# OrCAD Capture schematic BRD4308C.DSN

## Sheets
1 02: Module Pin Assignments: size A3; title: xGM210PB32 Wireless Gecko Module Radio Board; rev: A01; company: Silicon Labs; note: BRD4308C; note: TAB; note: JSH
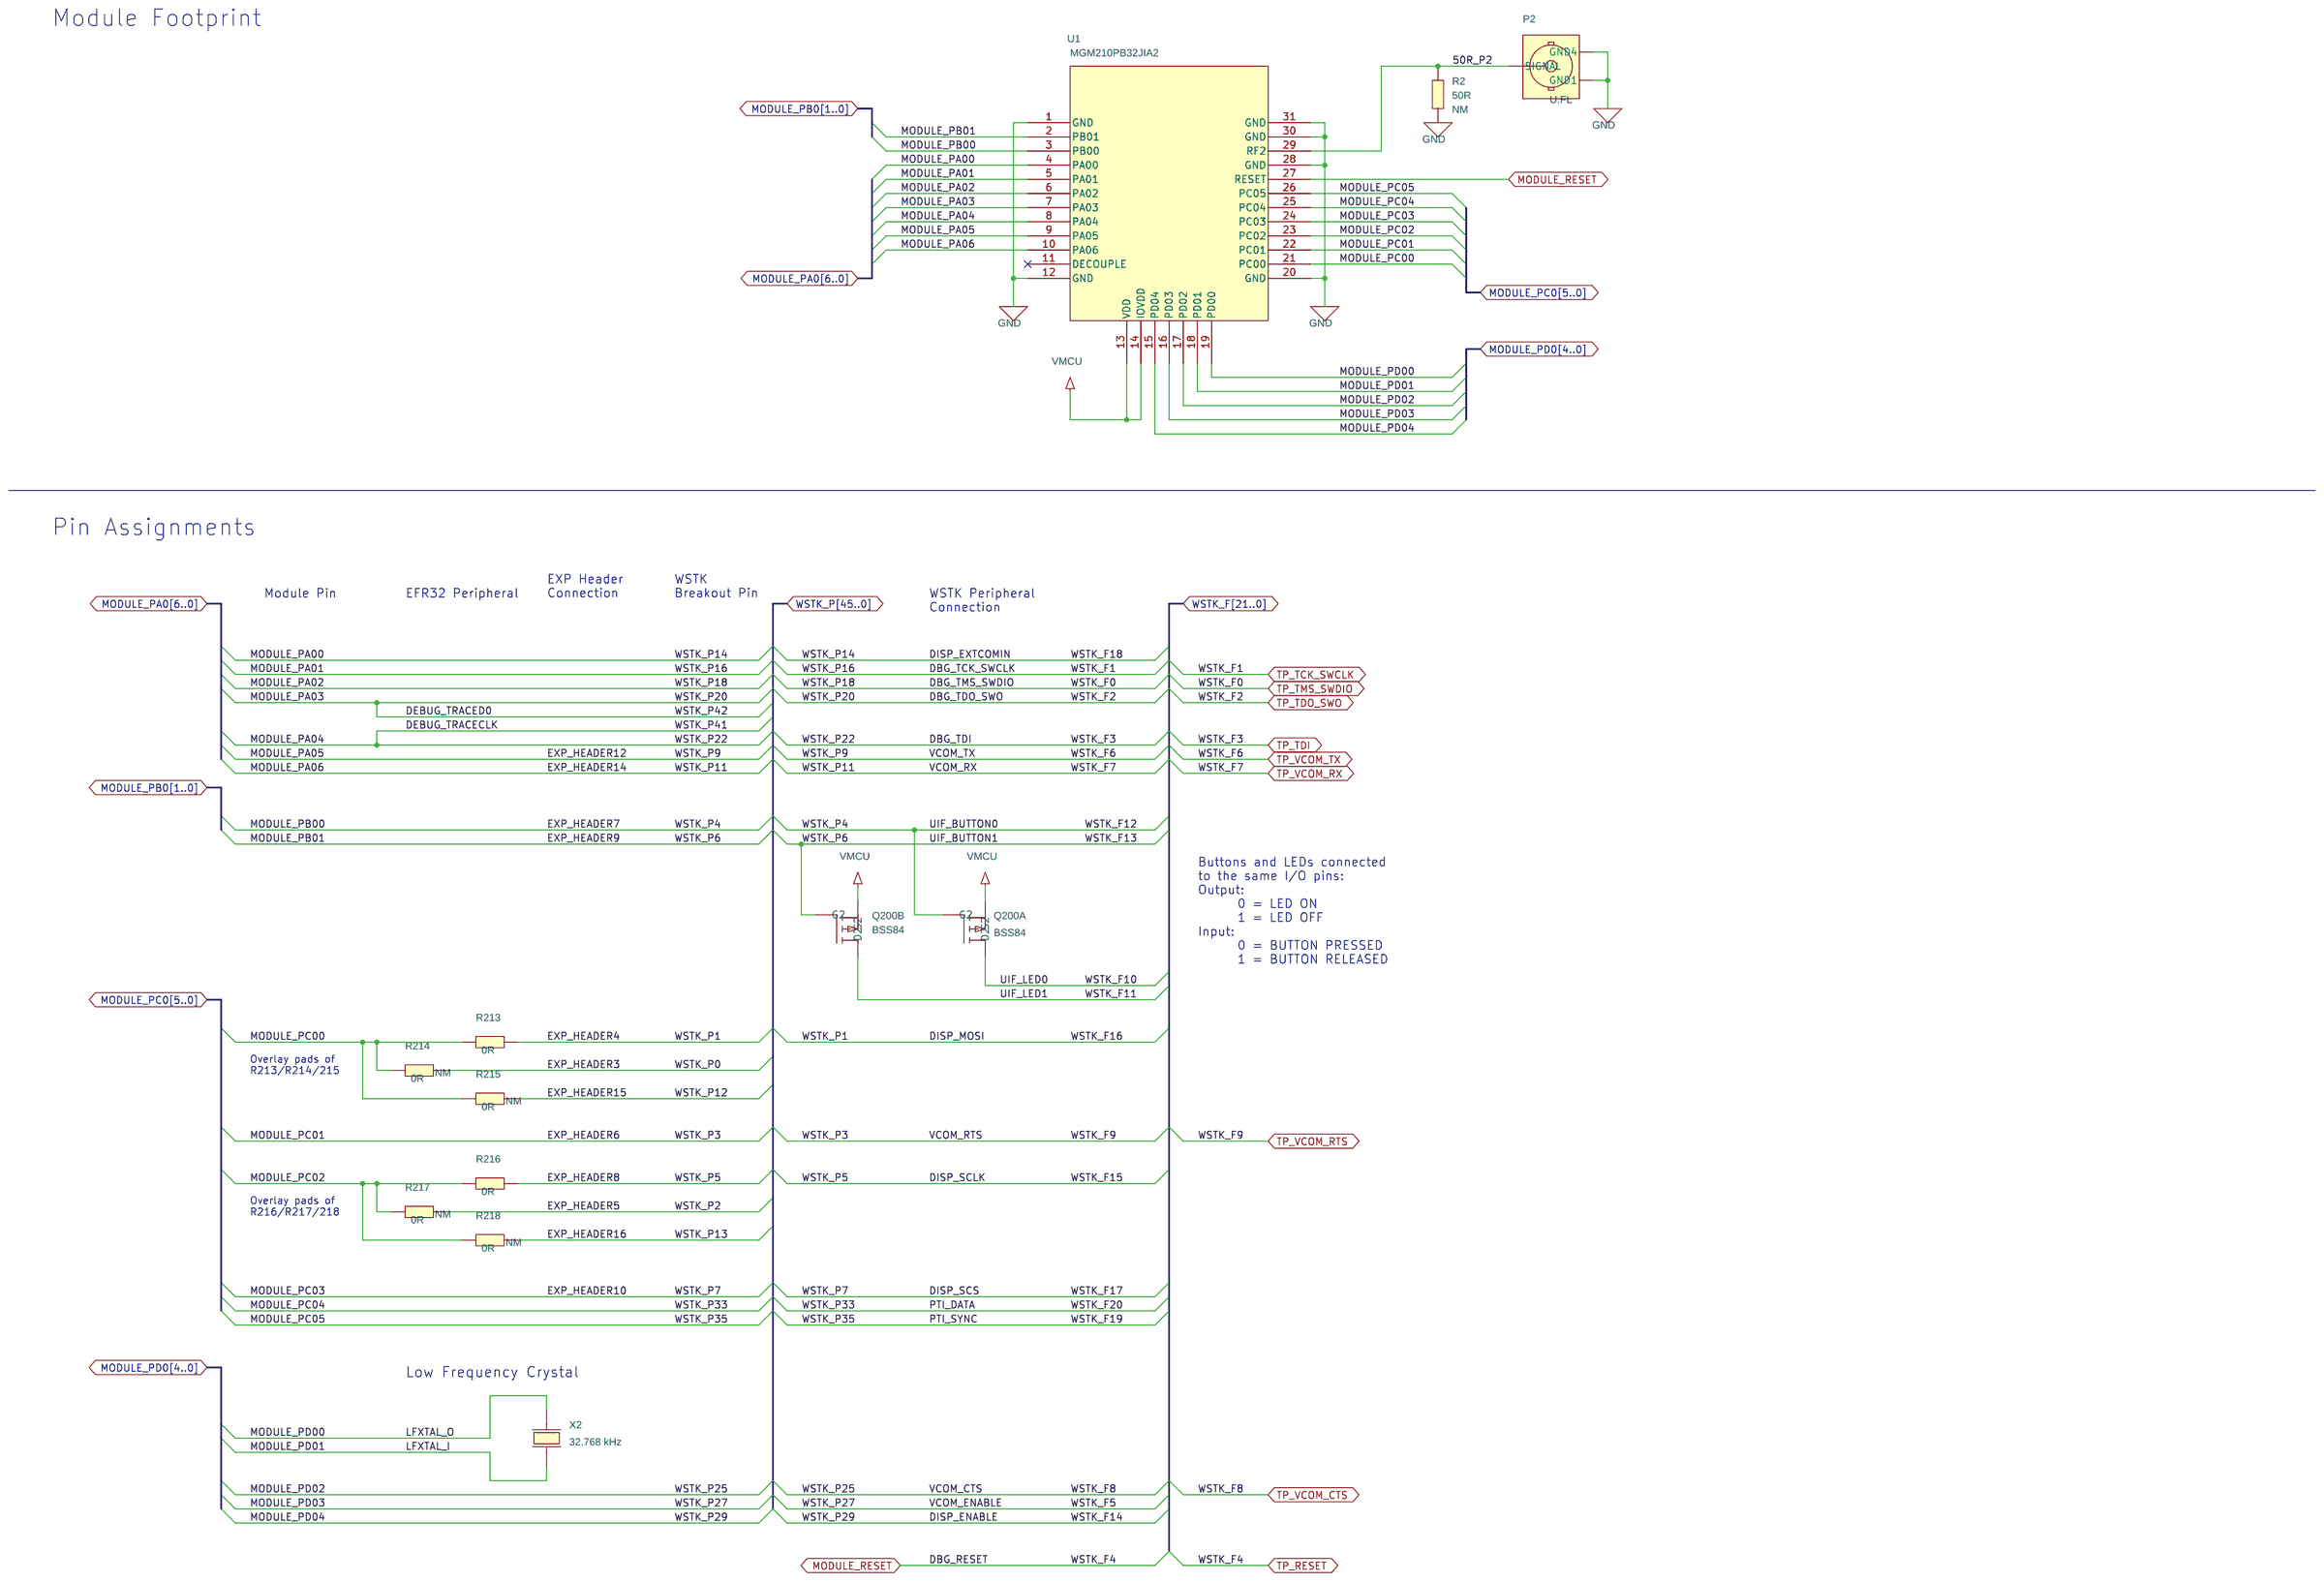
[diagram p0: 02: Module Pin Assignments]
2 01: Title Page
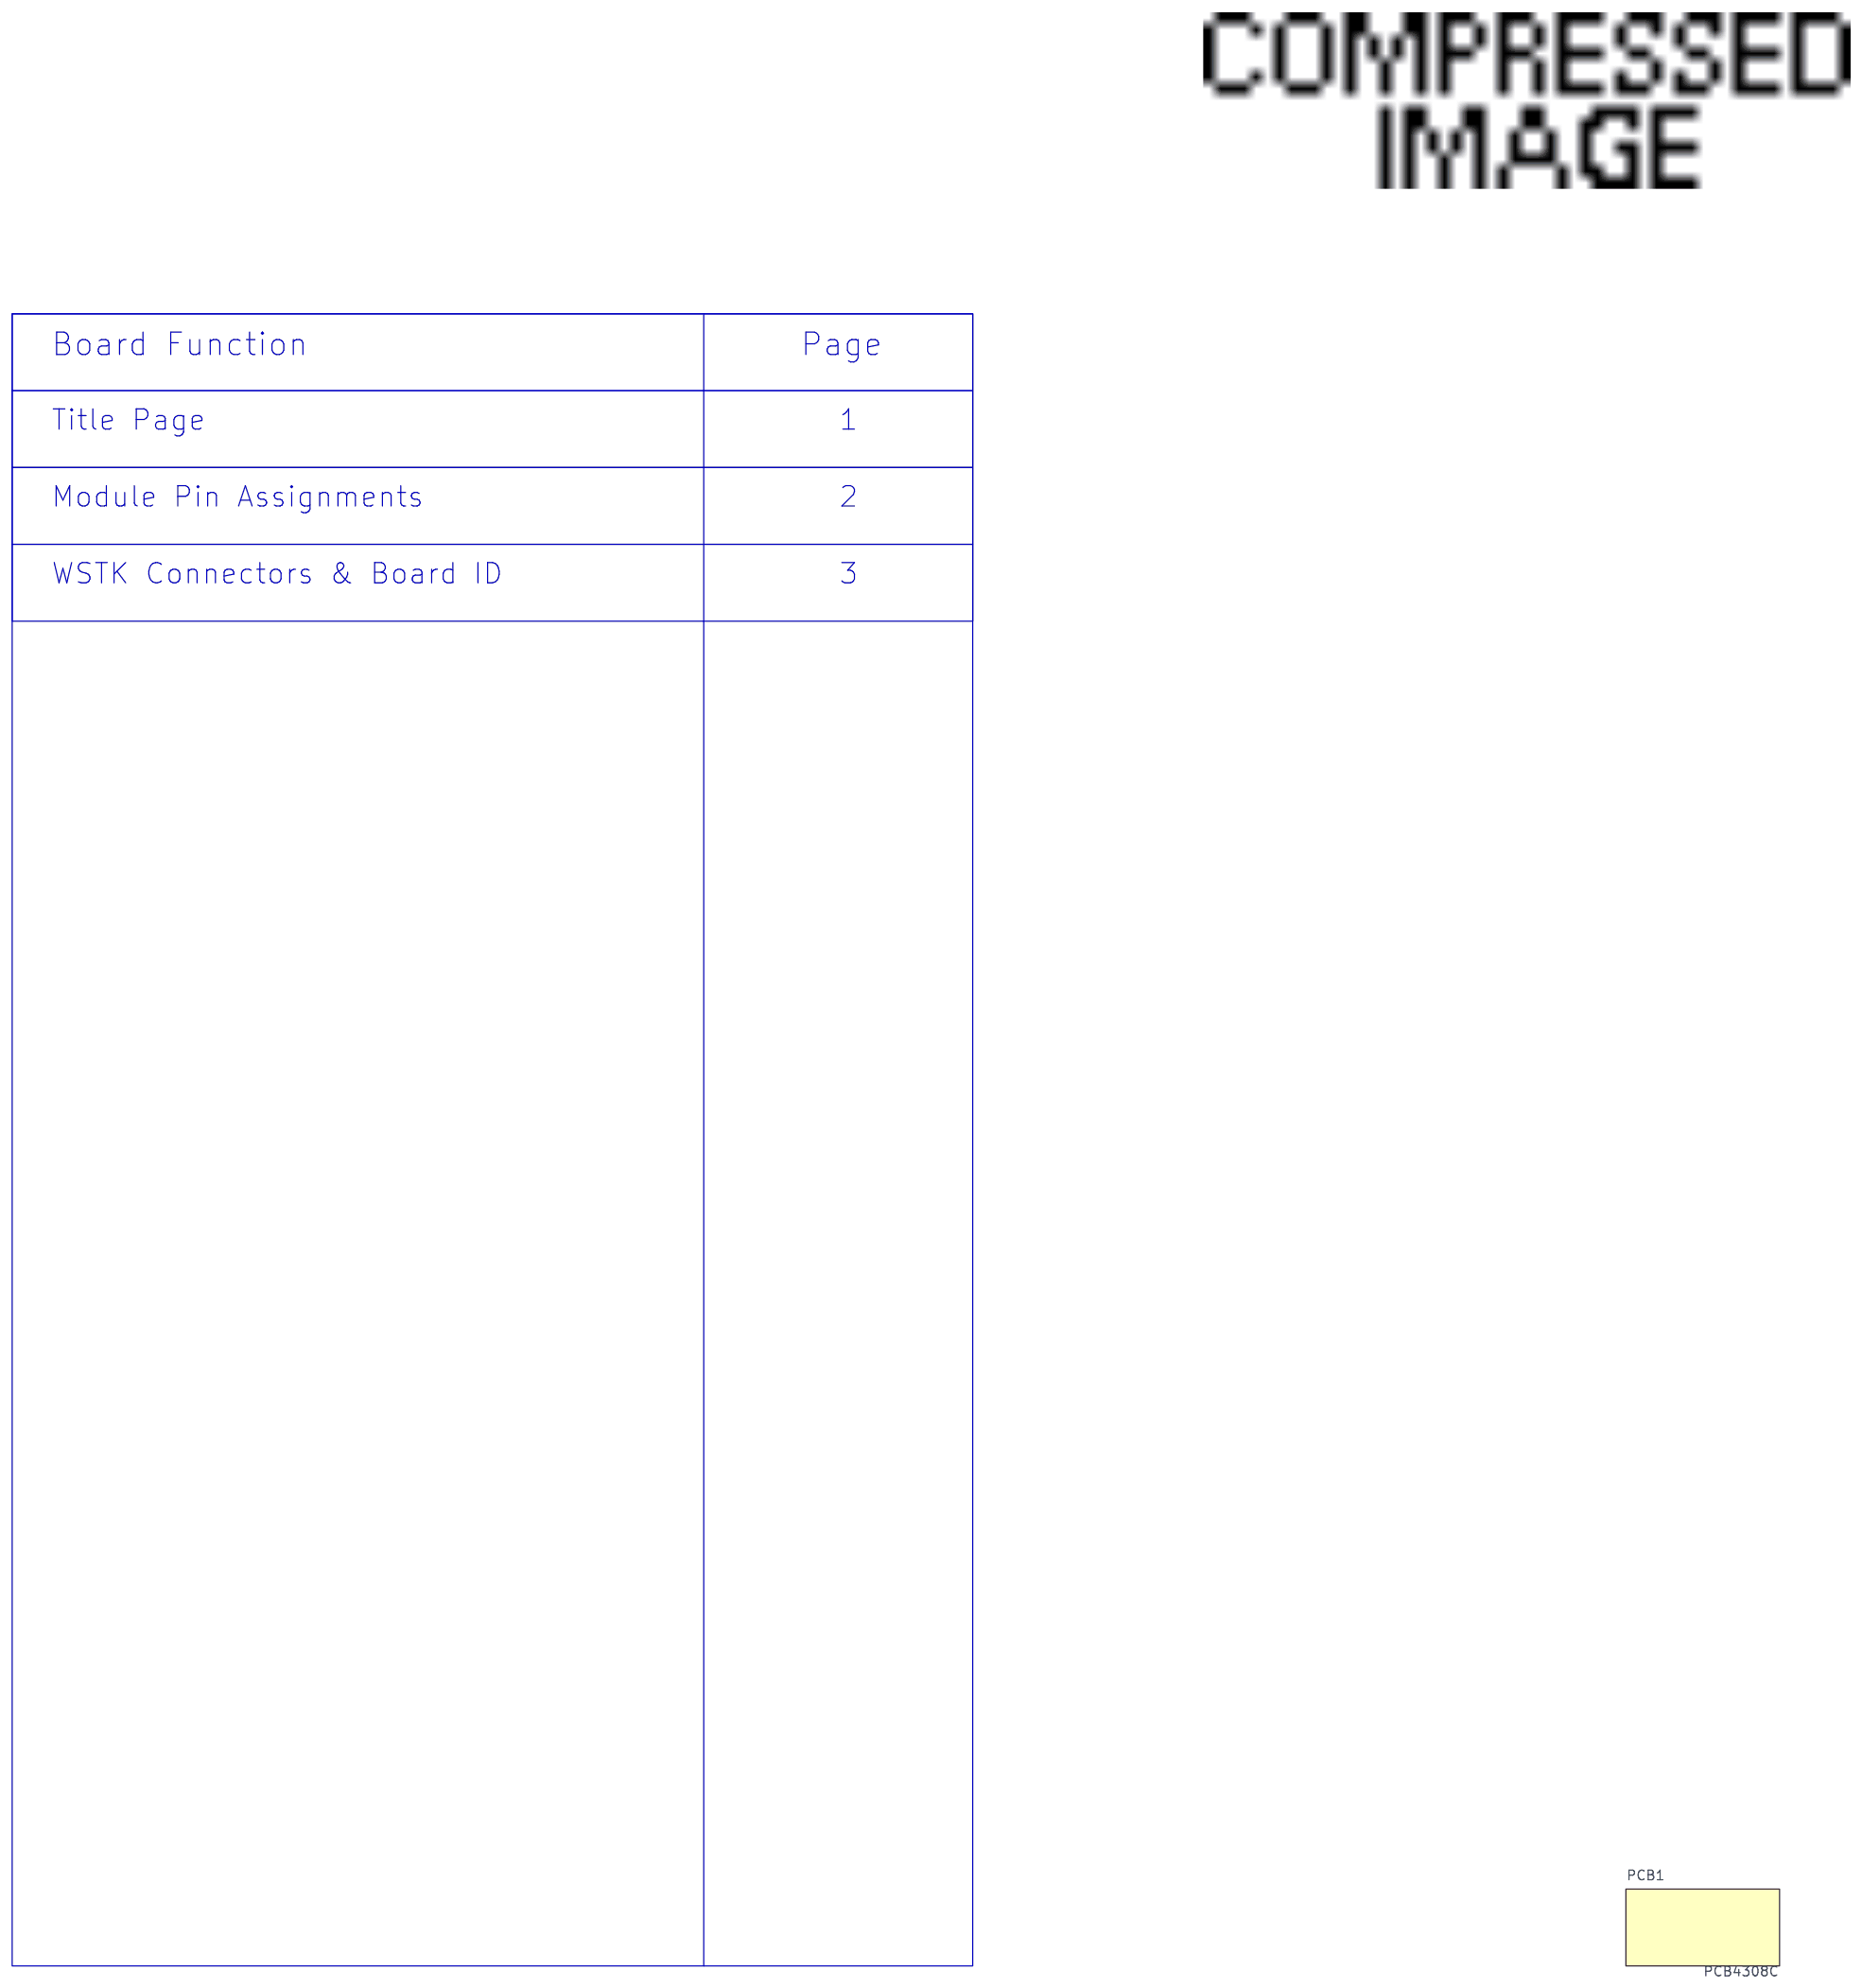
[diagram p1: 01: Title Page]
3 03: WSTK Connectors & Board ID: size A3
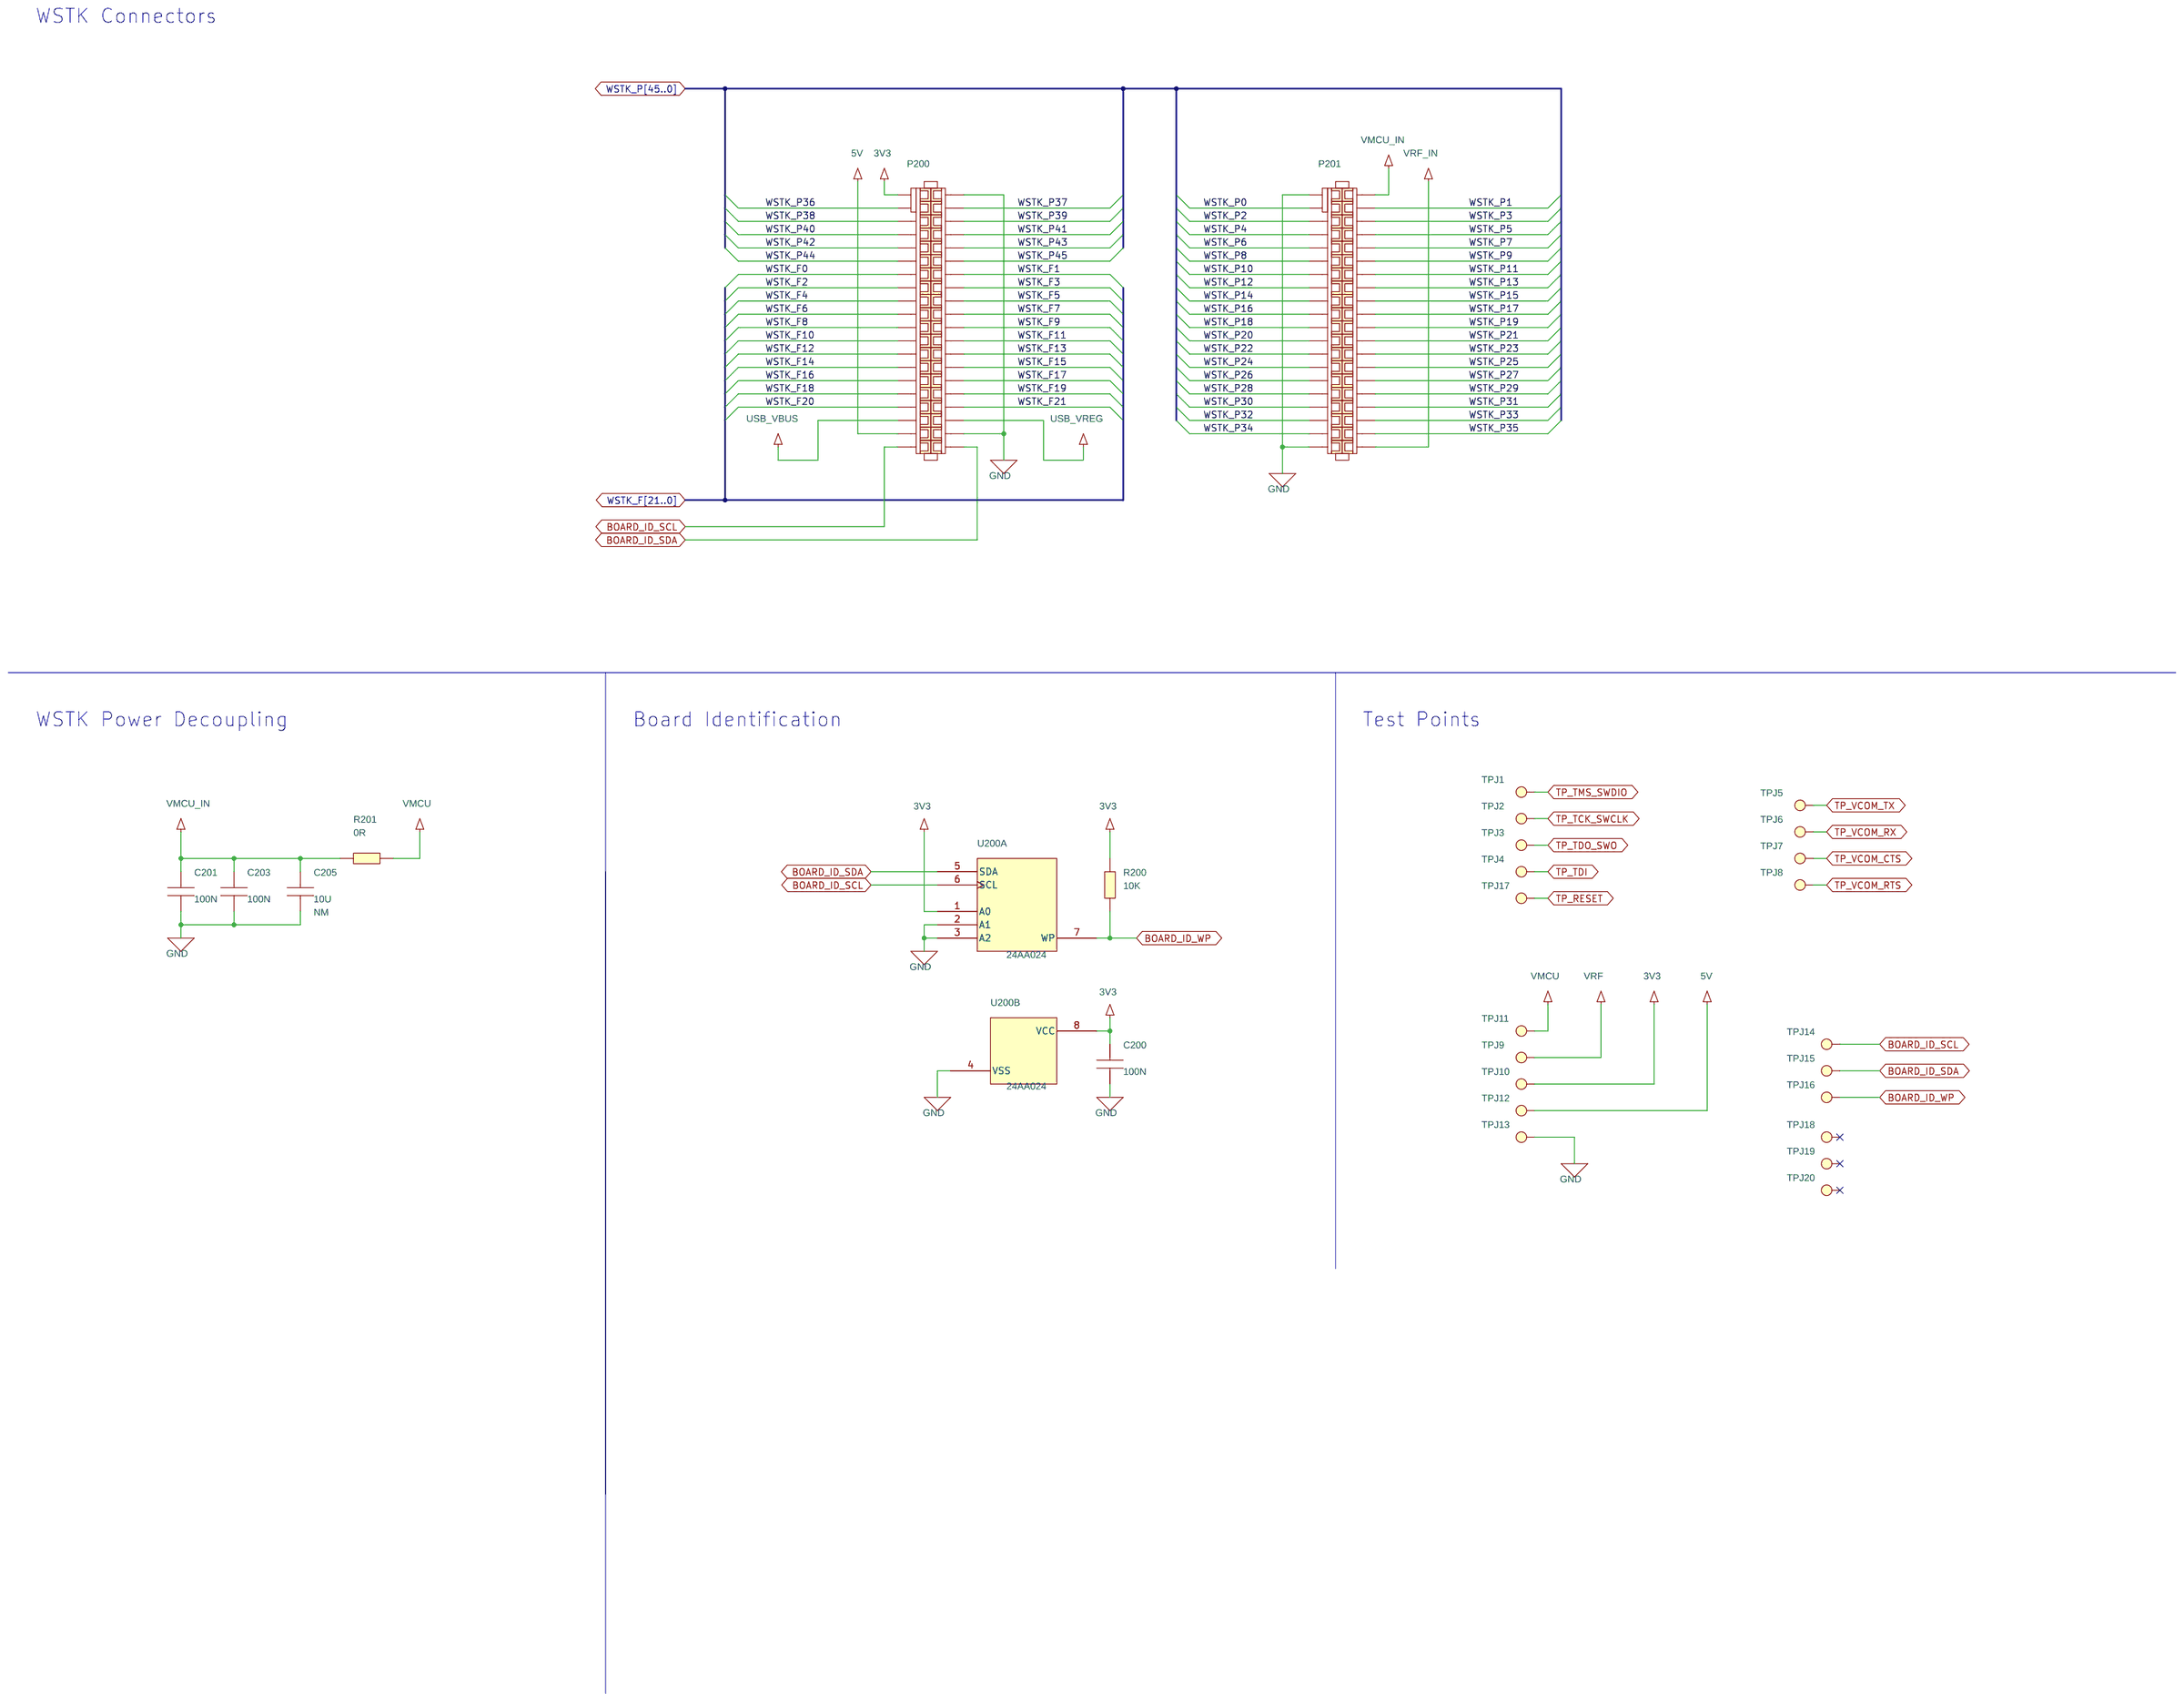
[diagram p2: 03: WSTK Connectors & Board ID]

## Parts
sheet 01: Title Page
PCB1  PCB4308C  [N/A]
sheet 02: Module Pin Assignments
P2  U.FL  [COAX_HIROSE_U.FL_CL331-0471]
Q200  BSS84  [SOT-363]  (sections A,B)
R2  50R  [R0402_L]
R213  0R  [R0402_L]
R214  0R  [R0402_L]
R215  0R  [R0402_L]
R216  0R  [R0402_L]
R217  0R  [R0402_L]
R218  0R  [R0402_L]
U1  MGM210PB32JIA2  [MODULE_xGM210P]
X2  32.768 kHz  [CRYSTAL_KDS_DST1610A]
sheet 03: WSTK Connectors & Board ID
C200  100N  [C0201_L]
C201  100N  [C0201_L]
C203  100N  [C0201_L]
C205  10U  [C0805_L]
P200  SOCKET_2X20_1.27MM_SMD  [SAMTEC_SFC-120-T2-L-D-A]
P201  SOCKET_2X20_1.27MM_SMD  [SAMTEC_SFC-120-T2-L-D-A]
R200  10K  [R0201_L]
R201  0R  [R0402_L]
TPJ1  TPJ_SMD  [TP_1.0_SMD]
TPJ2  TPJ_SMD  [TP_1.0_SMD]
TPJ3  TPJ_SMD  [TP_1.0_SMD]
TPJ4  TPJ_SMD  [TP_1.0_SMD]
TPJ5  TPJ_SMD  [TP_1.0_SMD]
TPJ6  TPJ_SMD  [TP_1.0_SMD]
TPJ7  TPJ_SMD  [TP_1.0_SMD]
TPJ8  TPJ_SMD  [TP_1.0_SMD]
TPJ9  TPJ_SMD  [TP_1.0_SMD]
TPJ10  TPJ_SMD  [TP_1.0_SMD]
TPJ11  TPJ_SMD  [TP_1.0_SMD]
TPJ12  TPJ_SMD  [TP_1.0_SMD]
TPJ13  TPJ_SMD  [TP_1.0_SMD]
TPJ14  TPJ_SMD  [TP_1.0_SMD]
TPJ15  TPJ_SMD  [TP_1.0_SMD]
TPJ16  TPJ_SMD  [TP_1.0_SMD]
TPJ17  TPJ_SMD  [TP_1.0_SMD]
TPJ18  TPJ_SMD  [TP_1.0_SMD]
TPJ19  TPJ_SMD  [TP_1.0_SMD]
TPJ20  TPJ_SMD  [TP_1.0_SMD]
U200  24AA024  [8-TDFN]  (sections A,B)

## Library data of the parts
PCB1 = PCB: Mfg #: PCB4308C Rev. A01; Price_1K: 1.0
P2 = HIROSE_U.FL
Q200 = BSS84DW
R2 = RESISTOR: Not Mounted: NM
R213 R216 = R0402
R214 R215 R217 R218 = R0402: Not Mounted: NM
U1 = xGM210P: Mfg #: MGM210PB32JIA2R
X2 = DST1610A: Mfg: Micro Crystal AG; Mfg #: CM8V-T1A-32.768KHZ-7PF-20PPM-TA-QC
C200 C201 C203 = C0201: Rating: 25V; Technology: X5R; Tolerance: 10%
C205 = CAPACITOR: Not Mounted: NM; Technology: X5R
P200 P201 = SOCKET_2X20_1.27MM_SMD: Mfg: WCON; Mfg #: 2344-220MS3CUNR4
R200 = R0201
R201 = RESISTOR
TPJ1-TPJ20 = TPJ_SMD
U200 = 24AA024: Mfg #: 24AA024T-I/MNY; Price_1K: 0.26

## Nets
3V3: C200.1 P200.1 R200.2 TPJ10.1(TP) U200.1(A0) U200.8(VCC)
5V: P200.37 TPJ12.1(TP)
GND: C200.2 C201.2 C203.2 C205.2 P2.2(GND1) P2.3(GND4) P200.2 P200.38 P201.1 P201.39 R2.1 TPJ13.1(TP) U1.1(GND) U1.12(GND) U1.20(GND) U1.28(GND) U1.30(GND) U1.31(GND) U200.2(A1) U200.3(A2) U200.4(VSS)
50R_P2: P2.1(SIGNAL) R2.2 U1.29(RF2)
BOARD_ID_SCL: P200.39 TPJ14.1(TP) U200.6(SCL)
BOARD_ID_SDA: P200.40 TPJ15.1(TP) U200.5(SDA)
BOARD_ID_WP: R200.1 TPJ16.1(TP) U200.7(WP)
MODULE_PA00: P200.31 P201.17 U1.4(PA00)
MODULE_PA01: P200.14 P201.19 TPJ2.1(TP) U1.5(PA01)
MODULE_PA02: P200.13 P201.21 TPJ1.1(TP) U1.6(PA02)
MODULE_PA03: P200.9 P200.15 P201.23 TPJ3.1(TP) U1.7(PA03)
MODULE_PA04: P200.8 P200.16 P201.25 TPJ4.1(TP) U1.8(PA04)
MODULE_PA05: P200.19 P201.12 TPJ5.1(TP) U1.9(PA05)
MODULE_PA06: P200.20 P201.14 TPJ6.1(TP) U1.10(PA06)
MODULE_PB00: P200.25 P201.7 Q200.2(G2) U1.3(PB00)
MODULE_PB01: P200.26 P201.9 Q200.5(G2) U1.2(PB01)
MODULE_PC00: R213.1 R214.1 R215.1 U1.21(PC00)
MODULE_PC01: P200.22 P201.6 TPJ8.1(TP) U1.22(PC01)
MODULE_PC02: R216.1 R217.1 R218.1 U1.23(PC02)
MODULE_PC03: P200.30 P201.10 U1.24(PC03)
MODULE_PC04: P200.33 P201.36 U1.25(PC04)
MODULE_PC05: P200.32 P201.38 U1.26(PC05)
MODULE_PD00: U1.19(PD00) X2.1
MODULE_PD01: U1.18(PD01) X2.2
MODULE_PD02: P200.21 P201.28 TPJ7.1(TP) U1.17(PD02)
MODULE_PD03: P200.18 P201.30 U1.16(PD03)
MODULE_PD04: P200.27 P201.32 U1.15(PD04)
MODULE_RESET: P200.17 TPJ17.1(TP) U1.27(RESET)
USB_VBUS: P200.35
USB_VREG: P200.36
VMCU: Q200.1(S2) Q200.4(S2) R201.2 TPJ11.1(TP) U1.13(VDD) U1.14(IOVDD)
VMCU_IN: C201.1 C203.1 C205.1 P201.2 R201.1
VRF: TPJ9.1(TP)
VRF_IN: P201.40
WSTK_F10: P200.23 Q200.6(D2)
WSTK_F11: P200.24 Q200.3(D2)
WSTK_F15: P200.28 P201.8 R216.2
WSTK_F16: P200.29 P201.4 R213.2
WSTK_F21: P200.34
WSTK_P0: P201.3 R214.2
WSTK_P2: P201.5 R217.2
WSTK_P8: P201.11
WSTK_P10: P201.13
WSTK_P12: P201.15 R215.2
WSTK_P13: P201.16 R218.2
WSTK_P15: P201.18
WSTK_P17: P201.20
WSTK_P19: P201.22
WSTK_P21: P201.24
WSTK_P23: P201.26
WSTK_P24: P201.27
WSTK_P26: P201.29
WSTK_P28: P201.31
WSTK_P30: P201.33
WSTK_P31: P201.34
WSTK_P32: P201.35
WSTK_P34: P201.37
WSTK_P36: P200.3
WSTK_P37: P200.4
WSTK_P38: P200.5
WSTK_P39: P200.6
WSTK_P40: P200.7
WSTK_P43: P200.10
WSTK_P44: P200.11
WSTK_P45: P200.12

Not connected (* = marked no-connect by the designer): TPJ18 1(TP)*; TPJ19 1(TP)*; TPJ20 1(TP)*; U1 11(DECOUPLE)*

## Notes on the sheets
sheet 1
- Module Footprint
- Pin Assignments
- EXP Header
  Connection
- WSTK
  Breakout Pin
- Module Pin
- EFR32 Peripheral
- WSTK Peripheral
  Connection
- Buttons and LEDs connected
  to the same I/O pins:
  Output:
        0 = LED ON
        1 = LED OFF
  Input:
        0 = BUTTON PRESSED
        1 = BUTTON RELEASED
- Overlay pads of
  R213/R214/215
- Overlay pads of
  R216/R217/218
- Low Frequency Crystal
sheet 2
- Board Function
- Page
- Title Page
- 1
- Module Pin Assignments
- 2
- WSTK Connectors & Board ID
- 3
sheet 3
- WSTK Connectors
- WSTK Power Decoupling
- Board Identification
- Test Points
